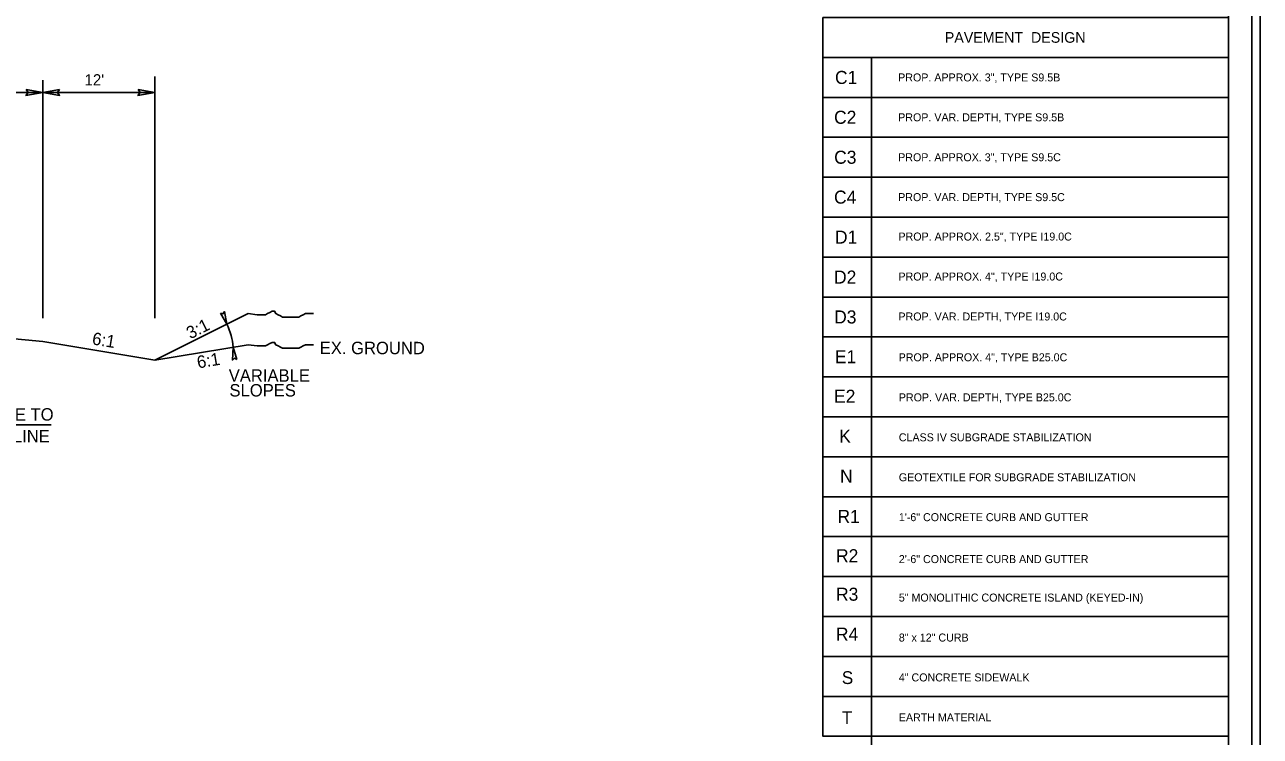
# Model space of a CAD drawing. Extents: x 2320980 to 2456309, y 595047 to 606177.
# Drawn here: x 2455913.1 to 2456045.5, y 595749.4 to 595825.6 of the extents above; entities that cross this region are included whole.
import ezdxf

# ---------------------------------------------------------------- set-up
doc = ezdxf.new("R2010")
doc.units = 0
for name, color, linetype in [('Old_Level_1', 7, 'Continuous'), ('Old_Level_11', 7, 'Continuous'), ('Old_Level_21', 7, 'Continuous'), ('Prop Dimension', 7, 'Continuous'), ('Prop Dimension Text', 7, 'Continuous'), ('Prop Pavement Schedule Description CELL', 7, 'Continuous'), ('Sheet Plan CELL', 7, 'Continuous'), ('Sheet Plot Border Inside CELL', 7, 'Continuous'), ('Sheet Plot Border Outside CELL', 7, 'Continuous'), ('Typical Hinge Slope Arterial CELL', 7, 'Continuous'), ('Typical Terminator CELL', 7, 'Continuous')]:
    doc.layers.add(name, color=color, linetype=linetype)

msp = doc.modelspace()

# ---------------------------------------------------------------- linework, layer by layer
at = {"layer": 'Old_Level_1'}
msp.add_line((2455907.04, 595792.4), (2455915.04, 595791.66), dxfattribs=at)
at = {"layer": 'Old_Level_11'}
msp.add_lwpolyline([(2455925.24, 595818.65), (2455927.04, 595818.34), (2455925.23, 595818.02), (2455925.46, 595818.34)], close=True, dxfattribs=at)
at = {"layer": 'Old_Level_21'}
for p, q in [((2455915.04, 595794.17), (2455915.04, 595819.67)), ((2455927.04, 595794.17), (2455927.04, 595820.03)), ((2455915.04, 595818.34), (2455907.04, 595818.34)), ((2455915.93, 595782.74), (2455906.73, 595782.74))]:
    msp.add_line(p, q, dxfattribs=at)
at = {"layer": 'Prop Dimension'}
for p, q in [((2456003.83, 595822.09), (2456003.83, 595728.59)), ((2455927.04, 595818.34), (2455915.04, 595818.34))]:
    msp.add_line(p, q, dxfattribs=at)
for points in [[(2455998.64, 595826.37), (2456042.11, 595826.37), (2456042.11, 595822.09), (2455998.64, 595822.09)], [(2455998.64, 595822.09), (2456042.11, 595822.09), (2456042.11, 595817.81), (2455998.64, 595817.81)], [(2455998.64, 595817.81), (2456042.11, 595817.81), (2456042.11, 595813.54), (2455998.64, 595813.54)], [(2455998.64, 595813.54), (2456042.11, 595813.54), (2456042.11, 595809.26), (2455998.64, 595809.26)], [(2455998.64, 595809.26), (2456042.11, 595809.26), (2456042.11, 595804.99), (2455998.64, 595804.99)], [(2455998.64, 595804.99), (2456042.11, 595804.99), (2456042.11, 595800.71), (2455998.64, 595800.71)], [(2455998.64, 595800.71), (2456042.11, 595800.71), (2456042.11, 595796.43), (2455998.64, 595796.43)], [(2455998.64, 595796.43), (2456042.11, 595796.43), (2456042.11, 595792.16), (2455998.64, 595792.16)], [(2455998.64, 595792.16), (2456042.11, 595792.16), (2456042.11, 595787.88), (2455998.64, 595787.88)], [(2455998.64, 595787.88), (2456042.11, 595787.88), (2456042.11, 595783.6), (2455998.64, 595783.6)], [(2455998.64, 595783.6), (2456042.11, 595783.6), (2456042.11, 595779.33), (2455998.64, 595779.33)], [(2455998.64, 595779.33), (2456042.11, 595779.33), (2456042.11, 595775.05), (2455998.64, 595775.05)], [(2455998.64, 595775.05), (2456042.11, 595775.05), (2456042.11, 595770.78), (2455998.64, 595770.78)], [(2455998.64, 595770.78), (2456042.11, 595770.78), (2456042.11, 595766.5), (2455998.64, 595766.5)], [(2455998.64, 595766.5), (2456042.11, 595766.5), (2456042.11, 595762.22), (2455998.64, 595762.22)], [(2455998.64, 595762.22), (2456042.11, 595762.22), (2456042.11, 595757.95), (2455998.64, 595757.95)], [(2455998.64, 595757.95), (2456042.11, 595757.95), (2456042.11, 595753.67), (2455998.64, 595753.67)], [(2455998.64, 595753.67), (2456042.11, 595753.67), (2456042.11, 595749.4), (2455998.64, 595749.4)]]:
    msp.add_lwpolyline(points, close=True, dxfattribs=at)
at = {"layer": 'Sheet Plan CELL'}
for points in [[(2456042.11, 595861.08), (2455742.1, 595861.08), (2455742.1, 595651.08), (2456042.11, 595651.08)], [(2455742.1, 595651.08), (2455742.1, 595861.07), (2456002.1, 595861.08), (2456002.1, 595831.07), (2456042.11, 595831.06), (2456042.11, 595651.08)]]:
    msp.add_lwpolyline(points, close=True, dxfattribs=at)
at = {"layer": 'Sheet Plot Border Inside CELL'}
msp.add_lwpolyline([(2455711.41, 595650.57), (2456044.6, 595650.58), (2456044.61, 595861.57), (2455711.41, 595861.57)], close=True, dxfattribs=at)
at = {"layer": 'Sheet Plot Border Outside CELL'}
msp.add_lwpolyline([(2455708.81, 595646.57), (2456045.51, 595646.57), (2456045.51, 595865.57), (2455708.81, 595865.57)], close=True, dxfattribs=at)
at = {"layer": 'Typical Hinge Slope Arterial CELL'}
for p, q in [((2455937.04, 595794.66), (2455927.04, 595789.66)), ((2455927.04, 595789.66), (2455915.04, 595791.66)), ((2455937.04, 595791.32), (2455927.04, 595789.66))]:
    msp.add_line(p, q, dxfattribs=at)
for points in [[(2455937.04, 595794.66), (2455938.02, 595794.53), (2455938.27, 595794.53), (2455938.64, 595794.53), (2455938.89, 595794.53), (2455939.13, 595794.66), (2455939.38, 595794.78), (2455939.62, 595794.9), (2455939.87, 595794.9), (2455939.99, 595794.66), (2455940.24, 595794.53), (2455940.49, 595794.41), (2455940.73, 595794.29), (2455940.98, 595794.29), (2455941.23, 595794.29), (2455941.47, 595794.29), (2455941.72, 595794.29), (2455941.97, 595794.29), (2455942.21, 595794.29), (2455942.46, 595794.29), (2455942.7, 595794.41), (2455942.95, 595794.53), (2455943.2, 595794.66), (2455943.57, 595794.66), (2455943.81, 595794.66), (2455944.06, 595794.66)], [(2455937.04, 595791.32), (2455938.02, 595791.2), (2455938.27, 595791.2), (2455938.64, 595791.2), (2455938.89, 595791.2), (2455939.13, 595791.32), (2455939.38, 595791.45), (2455939.62, 595791.57), (2455939.87, 595791.57), (2455939.99, 595791.32), (2455940.24, 595791.2), (2455940.49, 595791.08), (2455940.73, 595790.96), (2455940.98, 595790.96), (2455941.23, 595790.96), (2455941.47, 595790.96), (2455941.72, 595790.96), (2455941.97, 595790.96), (2455942.21, 595790.96), (2455942.46, 595790.96), (2455942.7, 595791.08), (2455942.95, 595791.2), (2455943.2, 595791.32), (2455943.57, 595791.32), (2455943.81, 595791.32), (2455944.06, 595791.32)]]:
    msp.add_lwpolyline(points, dxfattribs=at)
msp.add_arc((2455927.74, 595790.27), 7.74, 5.8103, 24.8127, dxfattribs=at)
at = {"layer": 'Typical Terminator CELL'}
for points in [[(2455913.24, 595818.65), (2455915.04, 595818.34), (2455913.23, 595818.02), (2455913.46, 595818.34)], [(2455916.83, 595818.65), (2455915.04, 595818.34), (2455916.84, 595818.02), (2455916.61, 595818.34)], [(2455934.06, 595794.69), (2455934.77, 595793.52), (2455934.49, 595794.87), (2455934.33, 595794.63)], [(2455935.83, 595789.75), (2455935.44, 595791.06), (2455935.36, 595789.68), (2455935.58, 595789.88)]]:
    msp.add_lwpolyline(points, close=True, dxfattribs=at)

# ---------------------------------------------------------------- texts
at = {"layer": 'Old_Level_1'}
msp.add_text('EX. GROUND', height=1.33, rotation=359.9103, dxfattribs=at).set_placement((2455944.71, 595790.32))
at = {"layer": 'Old_Level_21'}
for s, p in [('GRADE TO', (2455906.9, 595783.2)), ('THIS LINE', (2455907.29, 595780.87))]:
    msp.add_text(s, height=1.33, dxfattribs=at).set_placement(p)
at = {"layer": 'Prop Dimension Text'}
msp.add_text("12'", height=1.2, rotation=0.0002, dxfattribs=at).set_placement((2455919.51, 595819.09))
at = {"layer": 'Prop Pavement Schedule Description CELL'}
for s, height, p in [('PAVEMENT  DESIGN', 1.1403, (2456011.7, 595823.66)), ('C1', 1.397, (2455999.93, 595819.25)), ('PROP. APPROX. 3", TYPE S9.5B', 0.8552, (2456006.7, 595819.52)), ('C2', 1.397, (2455999.83, 595814.98)), ('PROP. VAR. DEPTH, TYPE S9.5B', 0.8552, (2456006.7, 595815.25)), ('C3', 1.397, (2455999.84, 595810.7)), ('PROP. APPROX. 3", TYPE S9.5C', 0.8552, (2456006.7, 595810.97)), ('C4', 1.397, (2455999.83, 595806.43)), ('PROP. VAR. DEPTH, TYPE S9.5C', 0.8552, (2456006.7, 595806.7)), ('D1', 1.397, (2455999.93, 595802.15)), ('PROP. APPROX. 2.5", TYPE I19.0C', 0.8552, (2456006.73, 595802.48)), ('D2', 1.397, (2455999.83, 595797.87)), ('PROP. APPROX. 4", TYPE I19.0C', 0.8552, (2456006.73, 595798.2)), ('D3', 1.397, (2455999.84, 595793.6)), ('PROP. VAR. DEPTH, TYPE I19.0C', 0.8552, (2456006.73, 595793.92)), ('E1', 1.397, (2455999.92, 595789.34)), ('PROP. APPROX. 4", TYPE B25.0C', 0.8552, (2456006.75, 595789.55)), ('E2', 1.397, (2455999.83, 595785.11)), ('PROP. VAR. DEPTH, TYPE B25.0C', 0.8552, (2456006.77, 595785.26)), ('K', 1.4, (2456000.38, 595780.83)), ('CLASS IV SUBGRADE STABILIZATION', 0.8552, (2456006.77, 595780.98)), ('N', 1.4, (2456000.47, 595776.56)), ('GEOTEXTILE FOR SUBGRADE STABILIZATION', 0.8552, (2456006.77, 595776.7)), ('R1', 1.397, (2456000.2, 595772.24)), ('1\'-6" CONCRETE CURB AND GUTTER', 0.8552, (2456006.77, 595772.43)), ('R2', 1.397, (2456000.04, 595768.03)), ('2\'-6" CONCRETE CURB AND GUTTER', 0.8552, (2456006.77, 595767.94)), ('R3', 1.397, (2456000.04, 595763.91)), ('5" MONOLITHIC CONCRETE ISLAND (KEYED-IN)', 0.8552, (2456006.77, 595763.82)), ('R4', 1.397, (2456000.03, 595759.63)), ('8" x 12" CURB', 0.8552, (2456006.77, 595759.54)), ('S', 1.37, (2456000.66, 595754.99)), ('4" CONCRETE SIDEWALK', 0.8552, (2456006.77, 595755.27)), ('T', 1.37, (2456000.66, 595750.71)), ('EARTH MATERIAL', 0.8552, (2456006.77, 595750.99))]:
    msp.add_text(s, height=height, dxfattribs=at).set_placement(p)
at = {"layer": 'Typical Hinge Slope Arterial CELL'}
for s, rotation, p in [('3:1', 26.565, (2455930.84, 595791.89)), ('6:1', 350.5377, (2455920.25, 595791.37)), ('6:1', 9.4635, (2455931.67, 595788.78))]:
    msp.add_text(s, height=1.33, rotation=rotation, dxfattribs=at).set_placement(p)
for s, p in [('VARIABLE ', (2455934.96, 595787.36)), ('SLOPES', (2455935.04, 595785.78))]:
    msp.add_text(s, height=1.33, dxfattribs=at).set_placement(p)

doc.saveas('drawing.dxf')
